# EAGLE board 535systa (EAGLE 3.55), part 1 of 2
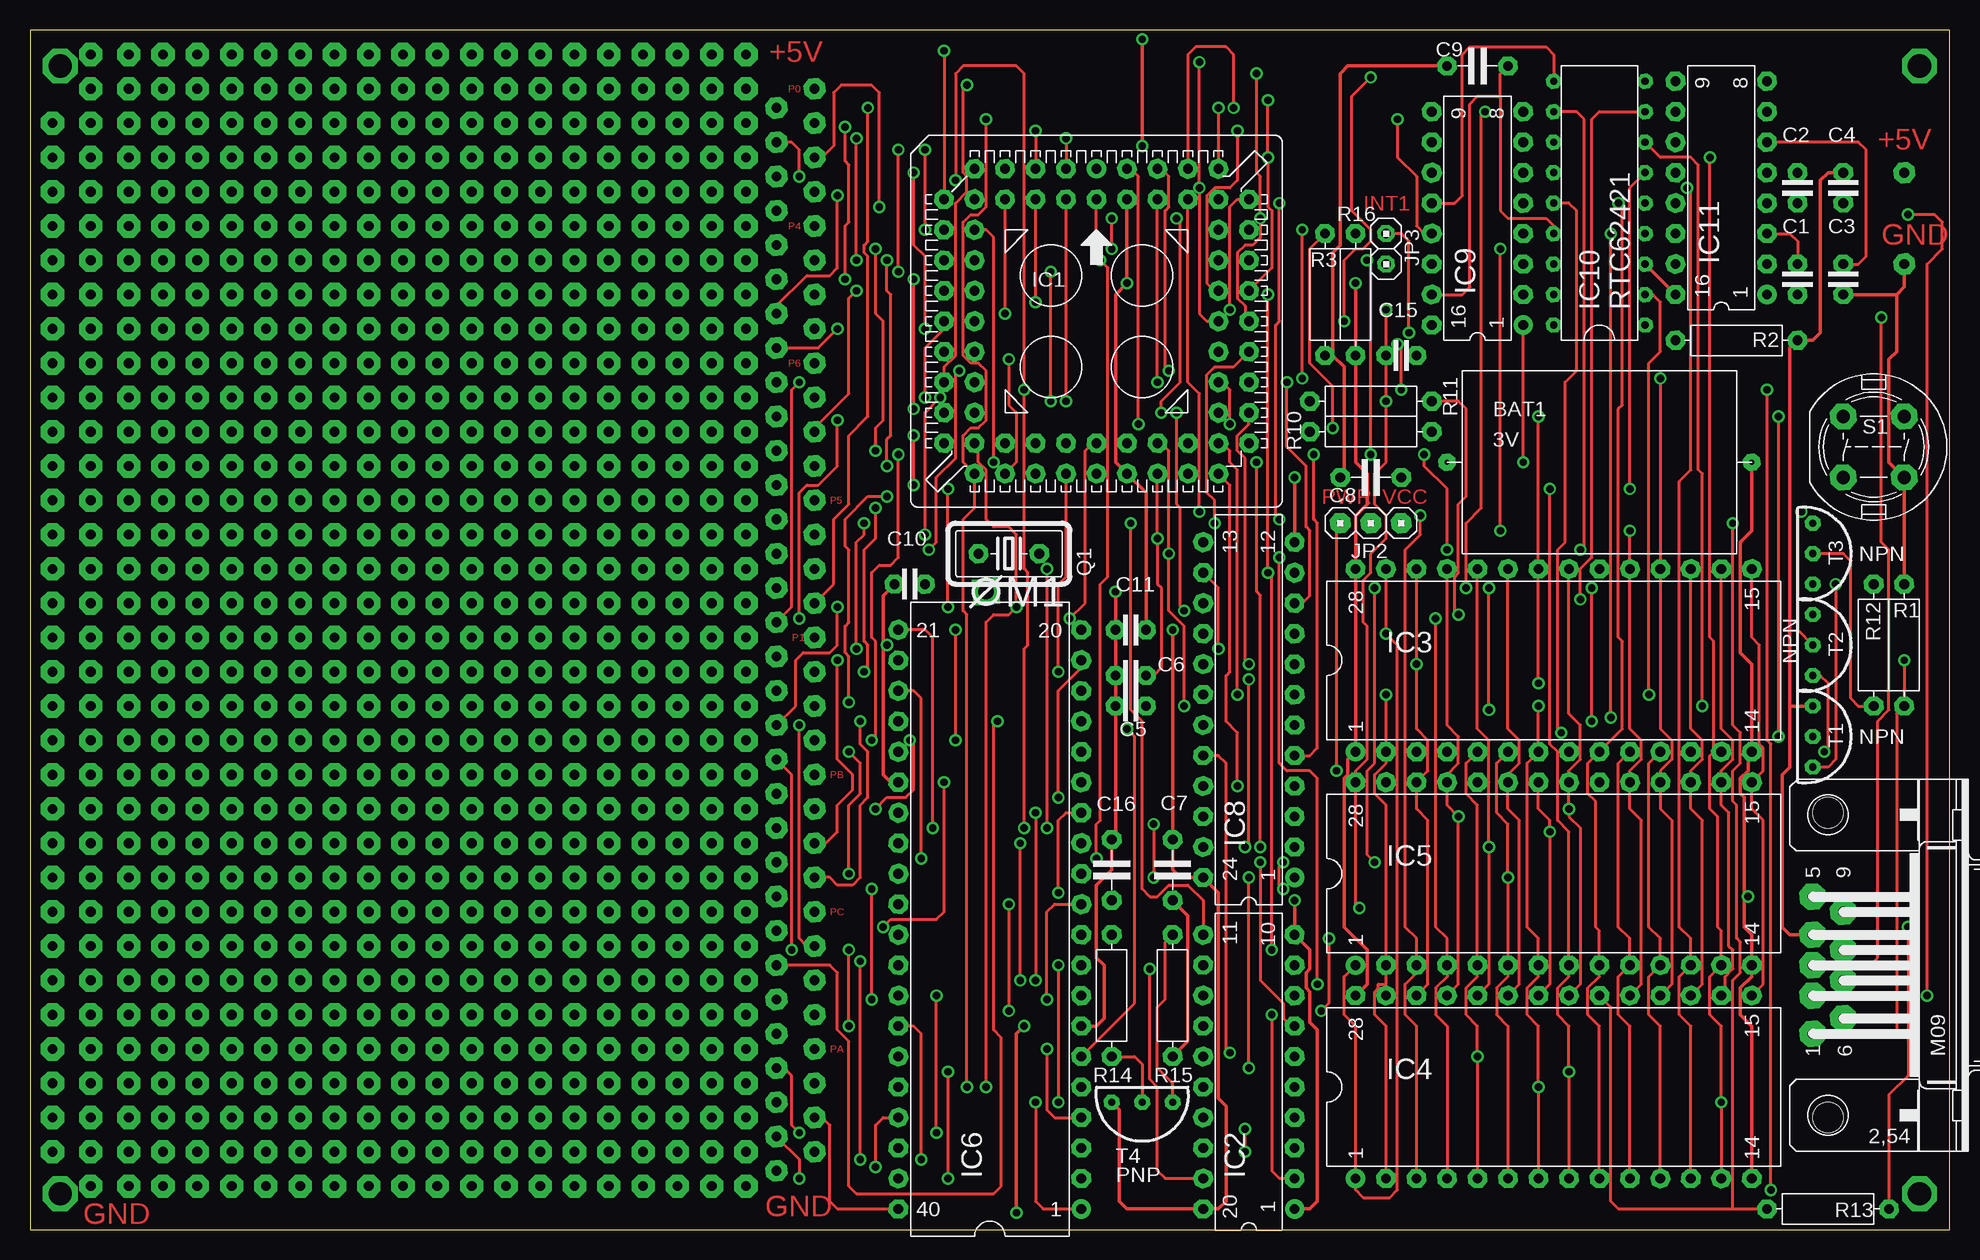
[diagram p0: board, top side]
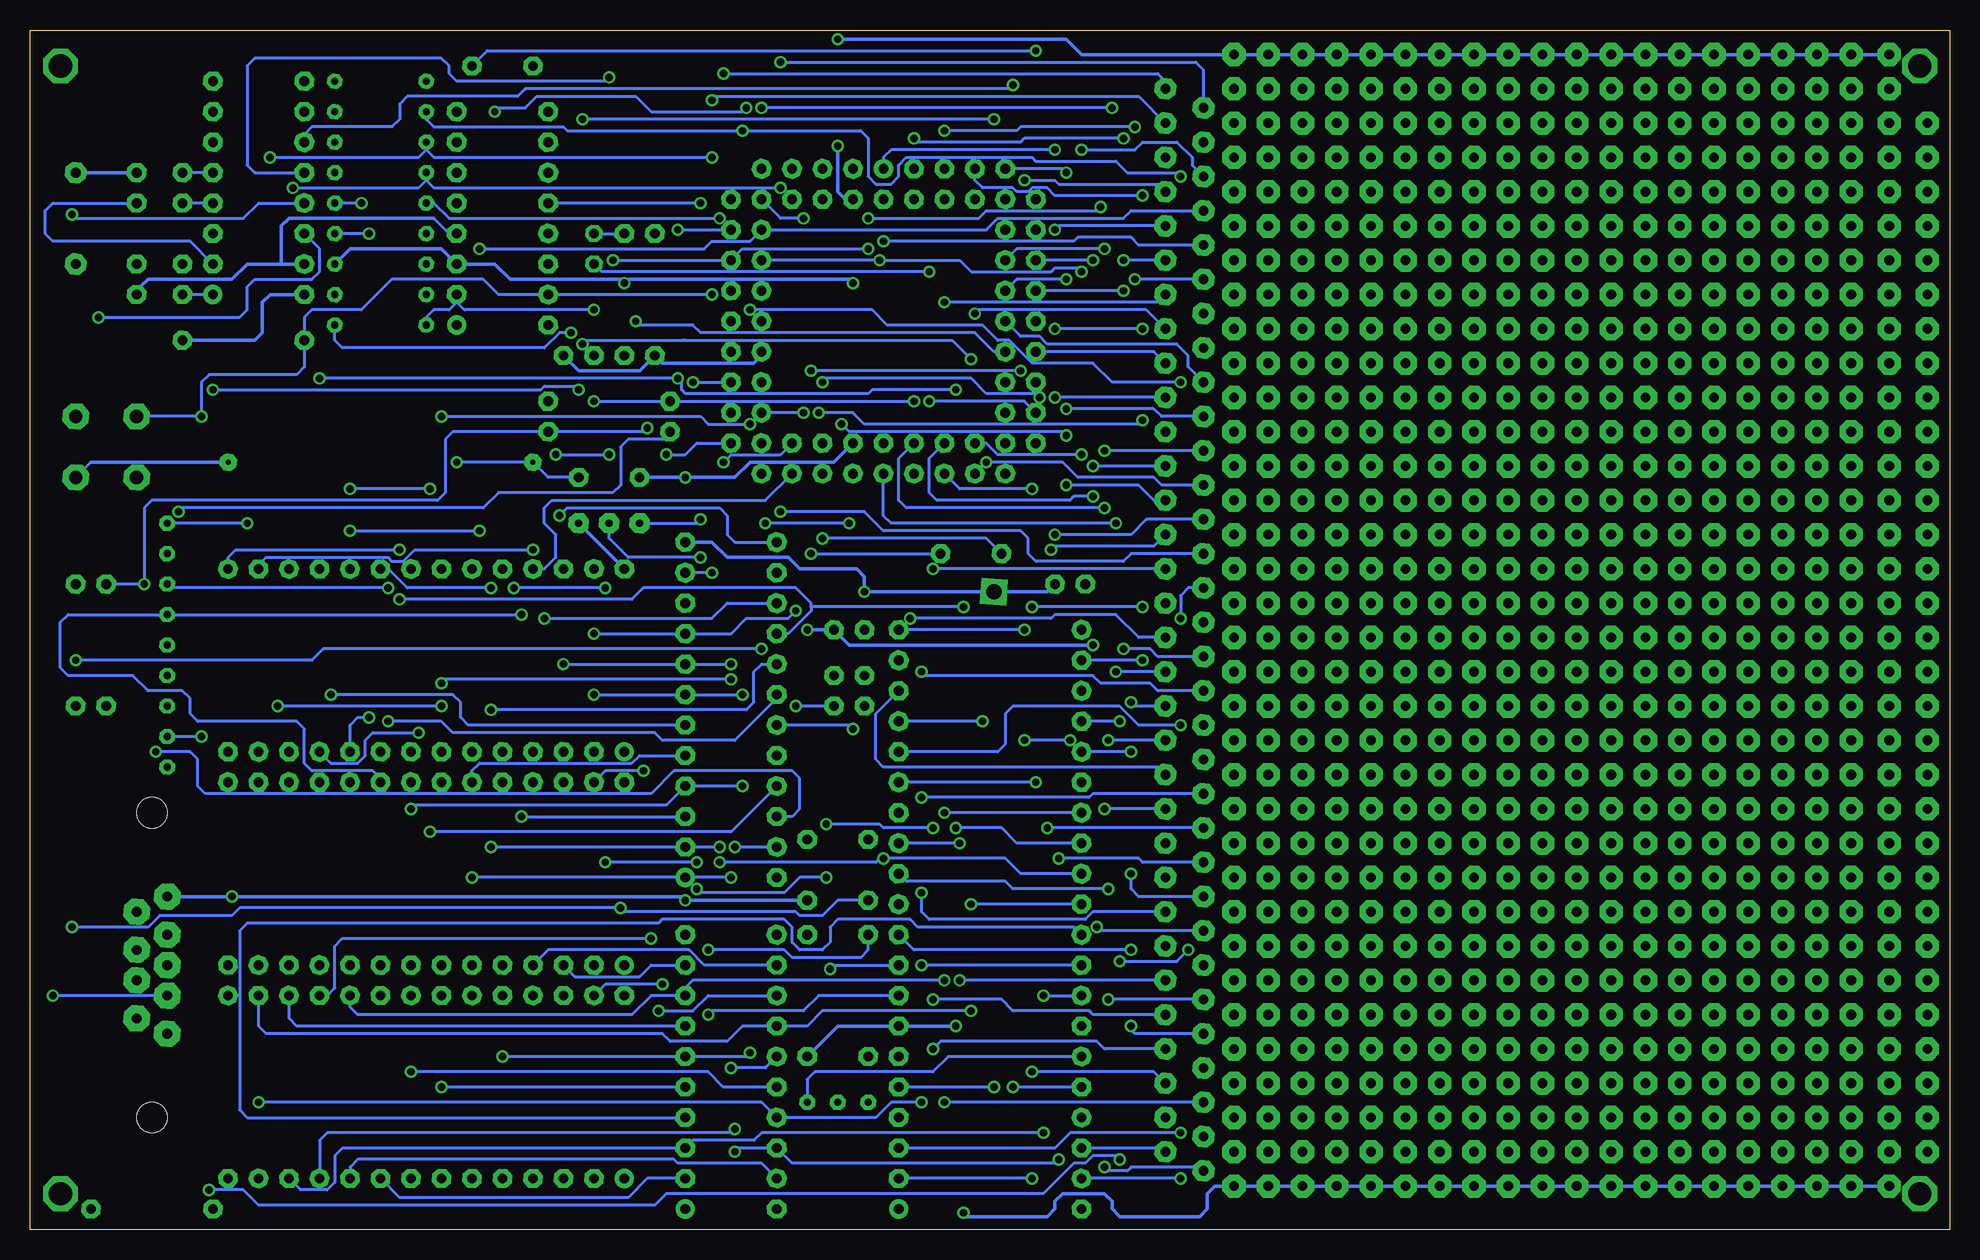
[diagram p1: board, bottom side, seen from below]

Size 159.99 x 99.97 mm. Coordinates in mm from the lower left corner, seen from the top.
Outline: 0,0 159.99,0 159.99,99.97 0,99.97 0,0
Copper layers used: Top, Bottom

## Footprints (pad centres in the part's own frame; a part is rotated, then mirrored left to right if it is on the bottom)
 = drill 0.406 pad 1.422 octagon:  -12.7,0;  12.7,0
2,5 = drill 0.813 pad 1.6 octagon:  -1.27,0;  1.27,0
5 = drill 0.813 pad 1.6 octagon:  -2.54,0;  2.54,0
8 = drill 0.813 pad 1.6 round:  0,12.7 | drill 0.813 pad 1.6 octagon:  0,10.16;  -2.54,12.7;  -2.54,10.16;  -5.08,12.7;  -5.08,10.16;  -7.62,12.7;  -7.62,10.16;  -10.16,12.7;  -12.7,10.16;  -10.16,10.16;  -12.7,7.62;  -10.16,7.62;  -12.7,5.08;  -10.16,5.08;  -12.7,2.54;  -10.16,2.54;  -12.7,0;  -10.16,0;  -12.7,-2.54;  -10.16,-2.54;  -12.7,-5.08;  -10.16,-5.08;  -12.7,-7.62;  -10.16,-7.62;  -12.7,-10.16;  -10.16,-12.7;  -10.16,-10.16;  -7.62,-12.7;  -7.62,-10.16;  -5.08,-12.7;  -5.08,-10.16;  -2.54,-12.7;  -2.54,-10.16;  0,-12.7;  0,-10.16;  2.54,-12.7;  2.54,-10.16;  5.08,-12.7;  5.08,-10.16;  7.62,-12.7;  7.62,-10.16;  10.16,-12.7;  12.7,-10.16;  10.16,-10.16;  12.7,-7.62;  10.16,-7.62;  12.7,-5.08;  10.16,-5.08;  12.7,-2.54;  10.16,-2.54;  12.7,0;  10.16,0;  12.7,2.54;  10.16,2.54;  12.7,5.08;  10.16,5.08;  12.7,7.62;  10.16,7.62;  12.7,10.16;  10.16,12.7;  10.16,10.16;  7.62,12.7;  7.62,10.16;  5.08,12.7;  5.08,10.16;  2.54,12.7;  2.54,10.16
L20 = drill 0.813 pad 1.6 round:  -11.43,-3.81 | drill 0.813 pad 1.6 octagon:  -8.89,-3.81;  -6.35,-3.81;  -3.81,-3.81;  -1.27,-3.81;  1.27,-3.81;  3.81,-3.81;  6.35,-3.81;  8.89,-3.81;  11.43,-3.81;  11.43,3.81;  8.89,3.81;  6.35,3.81;  3.81,3.81;  1.27,3.81;  -1.27,3.81;  -3.81,3.81;  -6.35,3.81;  -8.89,3.81;  -11.43,3.81
L28-6 = drill 0.813 pad 1.6 round:  -16.51,-7.62 | drill 0.813 pad 1.6 octagon:  -13.97,-7.62;  -11.43,-7.62;  -8.89,-7.62;  -6.35,-7.62;  -3.81,-7.62;  -1.27,-7.62;  1.27,-7.62;  3.81,-7.62;  6.35,-7.62;  8.89,-7.62;  11.43,-7.62;  13.97,-7.62;  16.51,-7.62;  16.51,7.62;  13.97,7.62;  11.43,7.62;  8.89,7.62;  6.35,7.62;  3.81,7.62;  1.27,7.62;  -1.27,7.62;  -3.81,7.62;  -6.35,7.62;  -8.89,7.62;  -11.43,7.62;  -13.97,7.62;  -16.51,7.62
L40 = drill 0.813 pad 1.6 round:  -24.13,-7.62 | drill 0.813 pad 1.6 octagon:  -21.59,-7.62;  -19.05,-7.62;  -16.51,-7.62;  -13.97,-7.62;  -11.43,-7.62;  -8.89,-7.62;  -6.35,-7.62;  -3.81,-7.62;  -1.27,-7.62;  1.27,-7.62;  3.81,-7.62;  6.35,-7.62;  8.89,-7.62;  11.43,-7.62;  13.97,-7.62;  16.51,-7.62;  19.05,-7.62;  21.59,-7.62;  24.13,-7.62;  24.13,7.62;  21.59,7.62;  19.05,7.62;  16.51,7.62;  13.97,7.62;  11.43,7.62;  8.89,7.62;  6.35,7.62;  3.81,7.62;  1.27,7.62;  -1.27,7.62;  -3.81,7.62;  -6.35,7.62;  -8.89,7.62;  -11.43,7.62;  -13.97,7.62;  -16.51,7.62;  -19.05,7.62;  -21.59,7.62;  -24.13,7.62
L24-3 = drill 0.813 pad 1.6 round:  -13.97,-3.81 | drill 0.813 pad 1.6 octagon:  -11.43,-3.81;  -8.89,-3.81;  -6.35,-3.81;  -3.81,-3.81;  -1.27,-3.81;  1.27,-3.81;  3.81,-3.81;  6.35,-3.81;  8.89,-3.81;  11.43,-3.81;  13.97,-3.81;  13.97,3.81;  11.43,3.81;  8.89,3.81;  6.35,3.81;  3.81,3.81;  1.27,3.81;  -1.27,3.81;  -3.81,3.81;  -6.35,3.81;  -8.89,3.81;  -11.43,3.81;  -13.97,3.81
L16 = drill 0.813 pad 1.6 round:  -8.89,-3.81 | drill 0.813 pad 1.6 octagon:  -6.35,-3.81;  -3.81,-3.81;  -1.27,-3.81;  1.27,-3.81;  3.81,-3.81;  6.35,-3.81;  8.89,-3.81;  8.89,3.81;  6.35,3.81;  3.81,3.81;  1.27,3.81;  -1.27,3.81;  -3.81,3.81;  -6.35,3.81;  -8.89,3.81
C62421 = drill 0.61 pad 1.27 octagon: 0 10.16,3.81; 1 7.62,3.81; 2 5.08,3.81; 3 2.54,3.81; 4 0,3.81; 5 -2.54,3.81; 6 -5.08,3.81; 7 -7.62,3.81; 8 -10.16,3.81;  -10.16,-3.81;  -7.62,-3.81;  -5.08,-3.81;  -2.54,-3.81;  0,-3.81;  2.54,-3.81;  5.08,-3.81;  7.62,-3.81;  10.16,-3.81
03 = drill 0.61 pad 1.676 octagon:  -2.54,0;  0,0;  2.54,0
02 = drill 0.813 pad 1.422 octagon:  -1.27,0;  1.27,0
TSTIFT = drill 1.27 pad 2.184 square:  0,0
18U-V = drill 0.813 pad 1.6 octagon:  -2.54,0;  2.54,0
10 = drill 0.813 pad 1.6 octagon:  -5.08,0;  5.08,0
6 = drill 1.118 pad 2.159 octagon:  -2.54,2.54;  2.54,2.54;  2.54,-2.54;  -2.54,-2.54
N-PNP = drill 0.61 pad 1.27 octagon:  -2.54,0;  0,0;  2.54,0
N-1 = drill 0.813 pad 1.778 octagon:  0,0
NN09 = drill 0.813 pad 2.184 octagon:  -5.715,1.27;  5.715,1.27;  0,1.27;  -2.54,1.27;  2.54,1.27;  -4.445,-1.27;  -1.27,-1.27;  1.27,-1.27;  4.445,-1.27 | hole 2.54: -12.7,0; 12.7,0

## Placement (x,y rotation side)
BAT1  3V  []  130.78,63.96 0 top
C1  10æ  [2,5]  147.29,79.2 90 top
C2  10æ  [2,5]  147.29,86.82 90 top
C3  10æ  [2,5]  151.1,79.2 90 top
C4  10æ  [2,5]  151.1,86.82 90 top
C5  22p  [2,5]  91.73,43.64 0 top
C6  22p  [2,5]  91.73,46.18 0 top
C7  100nF  [5]  95.22,29.98 270 top
C8  100nF  [5]  111.73,62.69 0 top
C9  100nF  [5]  120.62,96.98 0 top
C10  10æ  [2,5]  73.32,53.8 0 top
C11  680p  [2,5]  91.73,49.99 0 top
C15  10æF  [2,5]  114.27,72.85 0 top
C16  100nF  [5]  90.14,29.98 90 top
IC1  80C535  [8]  88.87,75.7 0 top
IC2  74373  [L20]  101.57,13.16 90 top
IC3  27C256  [L28-6]  126.97,47.45 0 top
IC4  28C256  [L28-6]  126.97,11.89 0 top
IC5  62256  [L28-6]  126.97,29.67 0 top
IC6  82C55A  [L40]  79.98,25.86 90 top
IC8  5C060  [L24-3]  101.57,43.32 90 top
IC9  MAX693  [L16]  120.62,84.28 90 top
IC10  RTC62421  [C62421]  130.78,85.55 90 top
IC11  MAX232  [L16]  140.94,86.82 90 top
JP2  CON03X1  [03]  111.73,58.88 0 top
JP3  CON02X1  [02]  113,81.74 90 top
M1  LTSTIFT  [TSTIFT]  79.67,53.16 0 top
Q1  12MHz  [18U-V]  81.57,56.34 0 top
R1  10k  [10]  156.18,48.72 90 top
R2  1k  [10]  142.21,74.12 0 top
R3  4k7  [10]  107.92,77.93 90 top
R10  4k7  [10]  111.73,66.5 0 top
R11  10k  [10]  111.73,69.04 0 top
R12  4k7  [10]  153.64,48.72 90 top
R13  10k  [10]  149.83,1.73 180 top
R14  4k7  [10]  90.14,19.51 90 top
R15  1k  [10]  95.22,19.51 90 top
R16  4k7  [10]  110.46,77.93 90 top
S1  DT6  [6]  153.64,65.23 0 top
T1  NPN  [N-PNP]  148.56,41.1 90 top
T2  NPN  [N-PNP]  148.56,48.72 90 top
T3  NPN  [N-PNP]  148.56,56.34 90 top
T4  PNP  [N-PNP]  92.68,10.62 0 top
U$1  PIN-1  [N-1]  65.38,95.07 0 top
U$2  PIN-1  [N-1]  62.2,93.48 0 top
U$3  PIN-1  [N-1]  65.38,92.21 0 top
U$4  PIN-1  [N-1]  62.2,90.63 0 top
U$5  PIN-1  [N-1]  65.38,89.36 0 top
U$6  PIN-1  [N-1]  62.2,87.77 0 top
U$7  PIN-1  [N-1]  65.38,86.5 0 top
U$8  PIN-1  [N-1]  62.2,84.91 0 top
U$9  PIN-1  [N-1]  65.38,49.35 0 top
U$10  PIN-1  [N-1]  62.2,47.76 0 top
U$11  PIN-1  [N-1]  65.38,46.49 0 top
U$12  PIN-1  [N-1]  62.2,44.91 0 top
U$13  PIN-1  [N-1]  65.38,43.64 0 top
U$14  PIN-1  [N-1]  62.2,42.05 0 top
U$15  PIN-1  [N-1]  65.38,40.78 0 top
U$16  PIN-1  [N-1]  62.2,39.19 0 top
U$17  PIN-1  [N-1]  65.38,83.64 0 top
U$18  PIN-1  [N-1]  62.2,82.05 0 top
U$19  PIN-1  [N-1]  65.38,80.78 0 top
U$20  PIN-1  [N-1]  62.2,79.2 0 top
U$21  PIN-1  [N-1]  65.38,77.93 0 top
U$22  PIN-1  [N-1]  62.2,76.34 0 top
U$23  PIN-1  [N-1]  65.38,75.07 0 top
U$24  PIN-1  [N-1]  62.2,73.48 0 top
U$25  PIN-1  [N-1]  65.38,60.78 0 top
U$26  PIN-1  [N-1]  62.2,59.19 0 top
U$27  PIN-1  [N-1]  65.38,57.92 0 top
U$28  PIN-1  [N-1]  62.2,56.34 0 top
U$29  PIN-1  [N-1]  65.38,55.07 0 top
U$30  PIN-1  [N-1]  62.2,53.48 0 top
U$31  PIN-1  [N-1]  65.38,52.21 0 top
U$32  PIN-1  [N-1]  62.2,50.62 0 top
U$33  PIN-1  [N-1]  65.38,72.21 0 top
U$34  PIN-1  [N-1]  62.2,70.62 0 top
U$35  PIN-1  [N-1]  65.38,69.35 0 top
U$36  PIN-1  [N-1]  62.2,67.77 0 top
U$37  PIN-1  [N-1]  65.38,66.5 0 top
U$38  PIN-1  [N-1]  62.2,64.91 0 top
U$39  PIN-1  [N-1]  65.38,63.64 0 top
U$40  PIN-1  [N-1]  62.2,62.05 0 top
U$41  PIN-1  [N-1]  65.38,15.06 0 top
U$42  PIN-1  [N-1]  62.2,13.47 0 top
U$43  PIN-1  [N-1]  65.38,12.2 0 top
U$44  PIN-1  [N-1]  62.2,10.62 0 top
U$45  PIN-1  [N-1]  65.38,9.35 0 top
U$46  PIN-1  [N-1]  62.2,7.76 0 top
U$47  PIN-1  [N-1]  65.38,6.49 0 top
U$48  PIN-1  [N-1]  62.2,4.9 0 top
U$49  PIN-1  [N-1]  65.38,37.92 0 top
U$50  PIN-1  [N-1]  62.2,36.33 0 top
U$51  PIN-1  [N-1]  65.38,35.06 0 top
U$52  PIN-1  [N-1]  62.2,33.48 0 top
U$53  PIN-1  [N-1]  65.38,32.21 0 top
U$54  PIN-1  [N-1]  62.2,30.62 0 top
U$55  PIN-1  [N-1]  65.38,29.35 0 top
U$56  PIN-1  [N-1]  62.2,27.76 0 top
U$57  PIN-1  [N-1]  65.38,26.49 0 top
U$58  PIN-1  [N-1]  62.2,24.9 0 top
U$59  PIN-1  [N-1]  65.38,23.63 0 top
U$60  PIN-1  [N-1]  62.2,22.05 0 top
U$61  PIN-1  [N-1]  65.38,20.78 0 top
U$62  PIN-1  [N-1]  62.2,19.19 0 top
U$63  PIN-1  [N-1]  65.38,17.92 0 top
U$64  PIN-1  [N-1]  62.2,16.33 0 top
U$65  PIN-1  [N-1]  156.18,88.09 0 top
U$66  PIN-1  [N-1]  156.18,80.47 0 top
X1  9 pol  [NN09]  149.83,22.05 90 top

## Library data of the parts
BAT1 = BATTERY
C1-C11 C15 C16 R1-R3 R10-R16 = DISCRETE
IC1 = INTEL
IC2 = 74XX
IC3 IC4 = MEMNEC
IC5 = MEMHITCH
IC6 = HARRIS
IC8 = PAL
IC9 IC11 = MAXIM
IC10 = Clock
JP2 JP3 M1 = CONNECT
Q1 = QUARTZ
S1 = KEY
T1-T4 = LINEAR
U$1-U$66 = CONQUICK
X1 = SUBD-A

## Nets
A0: IC2. IC3. IC4. IC5. IC6. IC10.
A1: IC2. IC3. IC4. IC5. IC6. IC10.
A2: IC2. IC3. IC4. IC5. IC10.
A3: IC2. IC3. IC4. IC5. IC10.
A4: IC2. IC3. IC4. IC5. IC8.
A5: IC2. IC3. IC4. IC5. IC8.
A6: IC2. IC3. IC4. IC5. IC8.
A7: IC2. IC3. IC4. IC5. IC8.
A8: IC1. IC3. IC4. IC5. IC8.
A9: IC1. IC3. IC4. IC5. IC8.
A10: IC1. IC3. IC4. IC5. IC8.
A11: IC1. IC3. IC4. IC5. IC8.
A12: IC1. IC3. IC4. IC5. IC8.
A13: IC1. IC3. IC4. IC5. IC8.
A14: IC1. IC3. IC4. IC5. IC8.
A15: IC1. IC8.
ALE: IC1. IC2.
CS_E^2: IC8. T3.
CS_PIO: IC6. IC8.
CS_PROM: IC3. IC8.
CS_RAM: IC8. T2.
CS_RTC: IC8. IC10.
GND: BAT1. C3. C5. C6. C7. C8. C9. C10. C11. C15. C16. IC1. IC2. IC3. IC4. IC5. IC6. IC8. IC9. IC11. M1. R1. R3. R15. S1. U$66. X1.
INT0: IC1.
INT1: IC1. JP3.
MODE: IC8. R1. X1.
N$1: BAT1. C8. IC9.
N$2: R3. R10. R12. T1.
N$3: R12. T3.
N$4: R10. T2.
N$5: IC4. R13. T3.
N$6: IC5. R11. T2.
N$7: C4. IC11.
N$8: C3. IC11.
N$9: IC6. R15. T4.
N$11: C1. IC11.
N$12: C1. IC11.
N$13: C2. IC11.
N$14: C2. IC11.
N$15: IC11. X1.
N$16: IC11. X1.
N$18: R14. T4.
N$19: IC10. JP3. R16.
N$21: IC4. JP2.
N$34: C5. IC1. Q1.
N$35: C6. IC1. Q1.
P00: IC1. IC2. IC3. IC4. IC5. IC6. IC10.4 U$1.
P01: IC1. IC2. IC3. IC4. IC5. IC6. IC10.3 U$2.
P02: IC1. IC2. IC3. IC4. IC5. IC6. IC10.2 U$3.
P03: IC1. IC2. IC3. IC4. IC5. IC6. IC10.1 U$4.
P04: IC1. IC2. IC3. IC4. IC5. IC6. U$5.
P05: IC1. IC2. IC3. IC4. IC5. IC6. U$6.
P06: IC1. IC2. IC3. IC4. IC5. IC6. U$7.
P07: IC1. IC2. IC3. IC4. IC5. IC6. U$8.
P10: IC1. U$9.
P11: IC1. U$10.
P12: IC1. U$11.
P13: IC1. U$12.
P14: IC1. U$13.
P15: IC1. U$14.
P16: IC1. U$15.
P17: IC1. U$16.
P40: IC1. U$17.
P41: IC1. U$18.
P42: IC1. U$19.
P43: IC1. U$20.
P44: IC1. U$21.
P45: IC1. U$22.
P46: IC1. U$23.
P47: IC1. U$24.
P50: IC1. U$25.
P51: IC1. U$26.
P52: IC1. U$27.
P53: IC1. U$28.
P54: IC1. U$29.
P55: IC1. U$30.
P56: IC1. U$31.
P57: IC1. U$32.
P60: IC1. U$33.
P61: IC1. U$34.
P62: IC1. U$35.
P63: IC1. U$36.
P64: IC1. U$37.
P65: IC1. U$38.
P66: IC1. U$39.
P67: IC1. U$40.
PA0: IC6. U$41.
PA1: IC6. U$42.
PA2: IC6. U$43.
PA3: IC6. U$44.
PA4: IC6. U$45.
PA5: IC6. U$46.
PA6: IC6. U$47.
PA7: IC6. U$48.
PB0: IC6. U$49.
PB1: IC6. U$50.
PB2: IC6. U$51.
PB3: IC6. U$52.
PB4: IC6. U$53.
PB5: IC6. U$54.
PB6: IC6. U$55.
PB7: IC6. U$56.
PC0: IC6. U$57.
PC1: IC6. U$58.
PC2: IC6. U$59.
PC3: IC6. U$60.
PC4: IC6. U$61.
PC5: IC6. U$62.
PC6: IC6. U$63.
PC7: IC6. U$64.
PSEN: IC1. IC3. IC8.
PWR: IC5. IC9. IC10.0 JP2.
RD: IC1. IC6. IC8. IC10.
RESET: C9. IC1. IC8. IC9. IC10.5 R2. R14. S1. T1.
RXD: IC1. IC11.
TXD: IC1. IC11.
VAGND: IC1.
VAREF: IC1.
VCC: C4. C7. C10. C11. IC1. IC2. IC3. IC4. IC6. IC8. IC9. IC10. IC11. JP2. R2. R16. T1. T4. U$65. X1.
VN: IC4. IC5. IC8.
VPD: C15. C16. IC1. IC5. IC9. IC10.8 R11. R13.
WR: IC1. IC6. IC9.

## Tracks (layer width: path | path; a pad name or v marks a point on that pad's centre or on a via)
A0  (via drill 0.61 pad 1.02)
  Top 0.254: 133.32,4.27 133.32,16.97 132.37,17.92 132.37,21.09 133.32,22.05 133.32,24.27 132.37,25.22 132.37,38.87 133.32,39.83 | v93.32,21.73 93.32,12.52 93.95,11.89 93.95,4.9 94.59,4.27 97.76,4.27 | v131.74,42.68 v131.74,83.01
  Bottom 0.254: 97.76,4.27 99.03,5.54 106.02,5.54 106.34,5.85 132.69,5.85 133.32,5.22 133.32,4.27 | v93.32,21.73 93,22.05 87.6,22.05 | v131.74,42.68 132.69,42.68 133.32,42.05 133.32,39.83 | v131.74,83.01 134.59,83.01
A1  (via drill 0.61 pad 1.02)
  Top 0.254: 130.78,4.27 130.78,16.97 129.83,17.92 129.83,20.14 130.78,21.09 130.78,22.05 130.78,24.91 130.47,25.22 130.47,35.7 129.83,36.33 129.83,38.87 130.78,39.83 132.69,41.73 132.69,49.04 132.37,49.35 132.37,68.4 132.69,68.72 132.69,85.23 v132.37,85.55 | v103.48,17.92 103.48,4.9 104.11,4.27 105.38,4.27
  Bottom 0.254: 105.38,4.27 108.56,4.27 110.15,2.68 129.2,2.68 130.78,4.27 | 87.6,19.51 94.27,19.51 95.54,18.24 103.16,18.24 v103.48,17.92 | v132.37,85.55 134.59,85.55
A2  (via drill 0.61 pad 1.02)
  Top 0.254: 128.24,4.27 v128.24,13.16 128.24,16.97 127.29,17.92 127.29,20.14 128.24,21.09 128.24,22.05 128.24,33.16 127.29,34.11 127.29,39.83 | 127.29,39.83 128.24,39.83 | v133.32,61.74 133.32,86.82 134.59,88.09 | v126.66,61.74 126.66,40.46 127.29,39.83
  Bottom 0.254: v128.24,13.16 103.48,13.16 102.21,11.89 97.76,11.89 | v126.66,61.74 v133.32,61.74
A3  (via drill 0.61 pad 1.02)
  Top 0.254: 125.7,4.27 v125.7,11.89 125.7,16.97 124.75,17.92 124.75,20.14 125.7,21.09 125.7,22.05 125.7,24.27 124.75,25.22 124.75,38.87 125.7,39.83 v125.7,43.64 | v139.36,43.64 139.36,63 139.04,63.32 139.04,88.72 138.4,89.36 135.86,89.36 134.59,90.63
  Bottom 0.254: 105.38,11.89 v125.7,11.89 | v125.7,43.64 v139.36,43.64
A4  (via drill 0.61 pad 1.02)
  Top 0.254: v101.57,13.48 v101.57,29.35 | 123.16,4.27 123.16,16.97 122.21,17.92 122.21,20.14 123.16,21.09 123.16,22.05 v123.16,29.35 123.16,33.79 122.21,34.75 122.21,38.87 123.16,39.83
  Bottom 0.254: v101.57,13.48 98.72,13.48 97.76,14.43 | v101.57,29.35 105.38,29.35 v123.16,29.35
A5  (via drill 0.61 pad 1.02)
  Top 0.254: 120.62,4.27 v120.62,14.43 120.62,16.97 119.67,17.92 119.67,20.14 120.62,21.09 120.62,22.05 120.62,35.38 119.67,36.33 119.67,38.87 120.62,39.83 | v99.99,14.74 99.67,15.06 99.67,38.87 99.03,39.51 97.76,39.51
  Bottom 0.254: v120.62,14.43 105.38,14.43 100.3,14.43 v99.99,14.74
A6  (via drill 0.61 pad 1.02)
  Top 0.254: 118.08,4.27 118.08,16.97 117.13,17.92 117.13,20.14 118.08,21.09 118.08,22.05 118.08,24.27 117.13,25.22 117.13,39.83 | 117.13,39.83 118.08,39.83 | 117.13,39.83 v117.13,50.94
  Bottom 0.254: 118.08,22.05 116.81,23.32 105.07,23.32 103.8,22.05 97.76,22.05 | v117.13,50.94 103.16,50.94 101.89,52.21 97.76,52.21
A7  (via drill 0.61 pad 1.02)
  Top 0.254: 115.54,4.27 115.54,16.97 114.59,17.92 114.59,20.46 115.54,21.41 115.54,22.05 115.54,24.27 114.59,25.22 114.59,39.83 | 114.59,39.83 115.54,39.83 | v115.86,59.51 115.86,57.93 114.59,56.65 114.59,39.83
  Bottom 0.254: 115.54,22.05 114.59,21.09 109.19,21.09 108.24,22.05 105.38,22.05 | v115.86,59.51 115.23,60.15 102.53,60.15 101.89,59.51 101.89,57.93 101.26,57.29 97.76,57.29
A8  (via drill 0.61 pad 1.02)
  Top 0.254: 118.08,19.51 119.04,20.46 v119.04,34.43 118.08,35.38 118.08,37.29 118.08,37.92 119.04,38.87 119.04,41.1 118.08,42.05 118.08,55.07
  Bottom 0.254: 96.49,63 98.72,60.78 116.5,60.78 117.13,60.15 117.13,58.88 116.18,57.93 116.18,56.02 117.13,55.07 118.08,55.07 | v119.04,34.43 105.38,34.43
A9  (via drill 0.61 pad 1.02)
  Top 0.254: 121.58,37.29 v121.58,31.89 121.58,20.46 120.62,19.51 | 121.58,37.29 120.62,37.29 | 121.58,37.29 121.58,40.78 120.62,41.73 120.62,55.07 | v102.21,63.96 102.21,53.16 102.53,52.85 v102.53,31.89
  Bottom 0.254: v102.21,63.96 101.57,64.59 97.45,64.59 96.49,65.55 | v102.53,31.89 105.38,31.89 v121.58,31.89
A10  (via drill 0.61 pad 1.02)
  Top 0.254: v100.62,36.97 100.62,41.42 99.67,42.37 99.67,46.18 99.99,46.5 99.99,62.05 99.03,63 | 128.24,19.51 129.2,20.46 129.2,33.48 128.24,34.43 v128.24,35.07 128.24,37.29 128.24,38.24 129.2,39.19 129.2,42.05 128.24,43 128.24,55.07
  Bottom 0.254: v100.62,36.97 105.38,36.97 106.97,35.38 127.93,35.38 v128.24,35.07
A11  (via drill 0.61 pad 1.02)
  Top 0.254: v106.97,64.59 106.97,59.19 107.29,58.88 107.29,40.15 106.65,39.51 105.38,39.51 | 123.16,19.51 124.12,20.46 124.12,34.11 123.16,35.07 123.16,37.29 123.16,37.92 124.12,38.87 124.12,40.78 123.16,41.73 123.16,55.07
  Bottom 0.254: v106.97,64.59 105.38,64.59 104.43,65.55 101.57,65.55 | 105.38,39.51 109.19,39.51 109.83,38.87 122.53,38.87 123.16,38.24 123.16,37.29
A12  (via drill 0.61 pad 1.02)
  Top 0.254: v100.62,44.59 100.62,63.32 99.99,63.96 99.99,64.91 99.35,65.55 99.03,65.55 | 113,4.27 113,16.97 112.05,17.92 112.05,19.82 112.37,20.14 112.37,20.46 113,20.46 113,22.05 113,35.38 112.05,36.33 112.05,37.92 113,38.87 113,39.83 v113,44.59
  Bottom 0.254: v100.62,44.59 105.38,44.59 v113,44.59
A13  (via drill 0.61 pad 1.02)
  Top 0.254: v101.57,47.13 101.26,47.45 101.26,64.28 100.62,64.91 100.62,66.18 101.57,67.13 101.57,68.08 | 115.54,19.51 116.5,20.46 116.5,34.11 115.54,35.07 115.54,37.29 116.5,38.24 116.5,40.78 115.54,41.73 v115.54,47.13 115.54,55.07
  Bottom 0.254: v101.57,47.13 105.38,47.13 v115.54,47.13
A14  (via drill 0.61 pad 1.02)
  Top 0.254: 110.46,22.05 109.51,21.09 109.51,17.92 110.46,16.97 110.46,4.27 110.46,3.31 111.1,2.68 113.32,2.68 113.96,3.31 113.96,48.72 v113,49.67 113,55.07 | v95.54,68.08 95.54,60.47 95.86,60.15 95.86,51.89 v96.18,51.57
  Bottom 0.254: v113,49.67 105.38,49.67 101.57,49.67 100.3,50.94 96.81,50.94 v96.18,51.57 | v95.54,68.08 99.03,68.08
A15  (via drill 0.61 pad 1.02)
  Top 0.254: v104.75,70.63 104.75,65.23 106.34,63.64 106.34,58.56 106.65,58.24 106.65,52.85 106.02,52.21 105.38,52.21
  Bottom 0.254: v104.75,70.63 101.57,70.63
ALE  (via drill 0.61 pad 1.02)
  Top 0.254: v98.72,58.88 98.72,60.78 98.08,61.42 98.08,71.26 98.72,71.9 100.3,71.9 101.57,73.16 | v91.73,58.88 91.73,43.32 92.68,42.37 92.68,28.4 93.32,27.76 93.95,27.76 94.91,28.72 96.49,28.72 97.76,27.45 97.76,24.59
  Bottom 0.254: v91.73,58.88 v98.72,58.88
CS_E^2  (via drill 0.61 pad 1.02)
  Top 0.254: v130.15,42.37 v130.15,53.48
  Bottom 0.254: v130.15,42.37 125.7,42.37 124.75,41.42 107.92,41.42 107.29,40.78 101.26,40.78 97.76,44.27 97.76,44.59 | v130.15,53.48 148.25,53.48 148.56,53.8
CS_PIO  (via drill 0.61 pad 1.02)
  Top 0.254: 87.6,14.43 92.05,18.87 92.05,41.1 v91.41,41.73
  Bottom 0.254: v91.41,41.73 91.73,42.05 97.76,42.05
CS_PROM  (via drill 0.61 pad 1.02)
  Top 0.254: v121.58,43.32 v121.58,53.48
  Bottom 0.254: 130.78,55.07 130.15,55.07 128.56,53.48 v121.58,53.48 | v121.58,43.32 100.3,43.32 99.67,43.96 99.67,46.5 99.03,47.13 97.76,47.13
CS_RAM  (via drill 0.61 pad 1.02)
  Top 0.254: v149.52,39.83 149.83,40.15 149.83,45.54 149.2,46.18 148.56,46.18
  Bottom 0.254: 97.76,34.43 96.49,34.43 95.86,35.07 95.86,37.61 96.49,38.24 106.34,38.24 108.24,36.33 145.39,36.33 146.02,36.97 146.02,39.19 146.66,39.83 v149.52,39.83
CS_RTC  (via drill 0.61 pad 1.02)
  Top 0.254: v134.91,44.59 134.91,72.21 135.86,73.16 135.86,77.29 135.23,77.93 134.59,77.93
  Bottom 0.254: v134.91,44.59 124.75,44.59 124.12,43.96 124.12,42.68 123.48,42.05 105.38,42.05
GND  (via drill 0.61 pad 1.02, 0.81 pad 1.93)
  Top 0.254: v143.17,27.76 142.85,27.76
  Top 0.305: R1. 156.18,62.69 154.91,63.96 154.91,72.53 155.55,73.16 155.55,77.93 | 143.48,4.27 143.48,16.97 142.53,17.92 142.53,20.14 143.48,21.09 143.48,22.05 143.48,24.59 142.85,25.22 142.85,27.76 142.85,36.02 142.53,36.33 142.53,37.61 143.17,38.24 143.17,39.51 143.48,39.83 143.48,47.13 142.53,48.08 142.53,57.29 143.48,58.24 BAT1. | 155.55,77.93 151.1,77.93 | 105.38,57.29 v105.38,62.69 | 108.56,72.85 108.56,81.42 109.19,82.05 109.19,96.34 109.83,96.98 118.08,96.98 | 109.19,62.69 109.51,63 109.51,71.9 108.56,72.85 | 108.56,72.85 107.92,72.85 | 105.38,1.73 106.65,1.73 107.29,2.36 107.29,16.65 106.65,17.29 106.65,19.82 106.34,20.14 106.34,21.41 106.65,21.73 106.65,23.32 105.38,24.59 v105.38,27.45 | C7. 96.49,26.18 96.49,15.7 95.22,14.43 | v90.46,53.16 90.46,49.99 90.46,46.18 90.46,43.64 90.46,32.84 C16. 90.14,29.98 88.87,28.72 88.87,22.68 89.51,22.05 89.51,17.6 88.87,16.97 87.6,16.97 | v82.21,1.41 82.21,16.33 v82.84,16.97 | U$66. 156.18,78.56 155.55,77.93
  Bottom 0.254: 150.79,78.56 151.1,78.56 151.1,77.93 | 126.34,84.28 125.07,83.01 124.43,83.01 | 154.91,63.96 156.18,62.69 | v105.38,27.45 105.7,27.76
  Bottom 0.305: 150.79,78.56 150.15,79.2 143.17,79.2 141.9,80.47 137.13,80.47 139.04,80.47 139.04,83.64 138.4,84.28 126.34,84.28 | BAT1. 154.91,63.96 | 148.56,27.76 v143.17,27.76 105.7,27.76 | 91.41,65.55 93,63.96 99.99,63.96 101.26,62.69 v105.38,62.69 109.19,62.69 | 99.03,73.16 99.03,72.85 99.67,72.21 107.29,72.21 107.92,72.85 109.19,71.58 114.27,71.58 C15. | 95.22,14.43 92.68,16.97 87.6,16.97 v82.84,16.97 | C10. 75.22,53.16 M1. v90.46,53.16 90.46,54.43 91.1,55.07 95.86,55.07 96.81,56.02 101.89,56.02 103.16,57.29 105.38,57.29 | C7. v105.38,27.45 | v5.05,3.63 v8.23,3.63 v11.09,3.63 v13.94,3.63 v16.8,3.63 v19.66,3.63 v22.52,3.63 v25.37,3.63 v28.23,3.63 v31.09,3.63 v33.95,3.63 v36.8,3.63 v39.66,3.63 v42.52,3.63 v45.38,3.63 v48.23,3.63 v51.09,3.63 v53.95,3.63 v56.81,3.63 v59.66,3.63 61.25,3.63 61.89,3 61.89,1.73 62.52,1.09 69.19,1.09 69.82,1.73 69.82,2.36 70.46,3 73.95,3 74.59,2.36 74.59,1.73 75.22,1.09 81.89,1.09 v82.21,1.41
INT1  (via drill 0.61 pad 1.02)
  Top 0.254: v85.06,69.04 v85.06,79.83
  Bottom 0.254: v85.06,69.04 77.13,69.04 76.17,68.08 | v85.06,79.83 112.37,79.83 113,80.47
MODE  (via drill 0.61 pad 1.02)
  Top 0.254: v99.03,48.4 99.03,53.48 97.76,54.75 | v156.18,47.45 156.18,43.64 155.55,43 155.55,16.65 154.91,16.01 148.88,16.01 148.56,16.33
  Bottom 0.254: v99.03,48.4 135.55,48.4 136.5,47.45 v156.18,47.45
N$1  (via drill 0.61 pad 1.02)
  Top 0.254: v124.43,63.96 124.43,75.39
  Bottom 0.254: C8. 116.81,62.69 118.08,63.96 v124.43,63.96
N$2  (via drill 0.61 pad 1.02)
  Top 0.254: v150.47,53.8 150.47,39.19 149.83,38.56 148.56,38.56 | v108.56,66.82 108.56,70.31 106.65,72.21 106.65,81.74 R3.
  Bottom 0.254: R12. v150.47,53.8 150.47,60.15 149.83,60.78 126.02,60.78 125.39,61.42 125.39,65.86 124.75,66.5 R10. 108.88,66.5 v108.56,66.82
N$3
  Top 0.254: 153.64,43.64 152.37,43.64 151.74,44.27 151.74,55.7 151.1,56.34 148.56,56.34
N$4  (via drill 0.61 pad 1.02)
  Top 0.254: v147.61,59.83 147.29,59.51 147.29,49.99 148.56,48.72
  Bottom 0.254: v147.61,59.83 147.29,60.15 122.21,60.15 120.94,61.42 111.42,61.42 110.78,62.05 110.78,65.23 110.15,65.86 107.29,65.86 106.65,66.5
N$5  (via drill 0.61 pad 1.02)
  Top 0.254: 141.9,1.73 132.37,1.73 131.74,2.36 131.74,18.56 130.78,19.51 | 141.9,1.73 R13. | v141.9,58.88 141.9,42.05 142.53,41.42 142.53,38.87 141.9,38.24 141.9,35.7 142.21,35.38 142.21,24.27 142.53,23.95 142.53,21.41 141.9,20.78 141.9,1.73
  Bottom 0.254: v141.9,58.88 T3.
N$6  (via drill 0.61 pad 1.02)
  Top 0.254: v119.04,51.26 118.72,51.57 118.72,54.43 119.04,54.75 119.04,60.47 119.67,61.1 119.67,68.4 119.04,69.04 R11.
  Bottom 0.254: 130.78,37.29 130.78,37.61 131.42,38.24 136.5,38.24 137.13,38.87 137.13,41.73 137.77,42.37 146.02,42.37 146.66,43 146.66,44.27 147.29,44.91 150.15,44.91 151.42,46.18 156.82,46.18 157.45,46.81 157.45,50.62 156.82,51.26 T2. v119.04,51.26
N$7
  Bottom 0.254: 144.75,80.47 146.66,82.37 158.09,82.37 158.72,83.01 158.72,84.91 158.09,85.55 151.1,85.55
N$8
  Top 0.254: C3. 152.37,80.47 153.01,81.1 153.01,89.99 152.37,90.63 144.75,90.63
N$9
  Top 0.254: R15. 94.59,23.95 94.59,19.19 93.95,18.56 93.95,13.48 95.22,12.21 T4.
  Bottom 0.254: 72.36,14.43 83.48,14.43 84.75,13.16 94.59,13.16 95.22,12.52 T4.
N$10  (via drill 0.81 pad 1.93)
  other vias: 59.66,95.07
N$11
  Bottom 0.254: 144.75,77.93 147.29,77.93
N$12
  Top 0.254: 144.75,83.01 146.66,83.01 147.29,82.37 C1.
N$13
  Bottom 0.254: 144.75,85.55 147.29,85.55
N$14
  Bottom 0.254: 144.75,88.09 C2.
N$15  (via drill 0.61 pad 1.02)
  Top 0.254: v156.5,84.6 158.72,84.6 159.36,83.96 159.36,81.74 158.09,80.47 v158.09,19.51
  Bottom 0.254: v156.5,84.6 156.18,84.28 142.21,84.28 140.94,85.55 137.13,85.55 | 148.56,19.51 v158.09,19.51
N$16  (via drill 0.61 pad 1.02)
  Top 0.254: v154.28,76.02 154.28,57.29 154.91,56.65 154.91,43.32 153.96,42.37 153.96,22.68 153.33,22.05 148.56,22.05
  Bottom 0.254: 137.13,83.01 135.86,81.74 135.86,79.83 136.5,79.2 141.26,79.2 141.9,78.56 141.9,76.66 142.53,76.02 v154.28,76.02
N$17  (via drill 0.81 pad 1.93)
  other vias: 59.66,92.21
N$18
  Top 0.254: 92.68,10.62 92.68,13.79 92.05,14.43 90.14,14.43
N$19  (via drill 0.61 pad 1.02)
  Top 0.254: v114.91,74.75 114.91,82.37 114.27,83.01 JP3.
  Bottom 0.254: v114.91,74.75 115.86,74.75 117.13,73.48 133.96,73.48 134.59,74.12 134.59,75.39 | JP3. R16.
N$20  (via drill 0.81 pad 1.93)
  other vias: 59.66,89.36
N$21  (via drill 0.61 pad 1.02)
  Top 0.254: v107.29,20.46 107.29,37.61 106.65,38.24 104.75,38.24 104.11,38.87 v104.11,56.02
  Bottom 0.254: v107.29,20.46 112.05,20.46 113,19.51 | v104.11,56.02 110.15,56.02 111.73,57.61 111.73,58.88
N$22  (via drill 1.93 pad 2.54)
  other vias: 157.45,3
N$23  (via drill 0.81 pad 1.93)
  other vias: 59.66,86.5
N$24  (via drill 0.81 pad 1.93)
  other vias: 59.66,83.64
N$25  (via drill 1.93 pad 2.54)
  other vias: 157.45,96.98
N$26  (via drill 1.93 pad 2.54)
  other vias: 2.51,3
N$27  (via drill 1.93 pad 2.54)
  other vias: 2.51,96.98
N$28  (via drill 0.81 pad 1.93)
  other vias: 59.66,80.78
N$29  (via drill 0.81 pad 1.93)
  other vias: 59.66,77.93
N$30  (via drill 0.81 pad 1.93)
  other vias: 59.66,75.07
N$31  (via drill 0.81 pad 1.93)
  other vias: 59.66,72.21
N$32  (via drill 0.81 pad 1.93)
  other vias: 59.66,69.35
N$33  (via drill 0.81 pad 1.93)
  other vias: 59.66,66.5
N$34  (via drill 0.61 pad 1.02)
  Top 0.254: 93.95,65.55 94.27,65.55 94.91,64.91 v94.91,56.34 94.91,51.57 96.18,50.3 v96.18,43.64
  Bottom 0.254: v94.91,56.34 Q1. | C5. v96.18,43.64
N$35  (via drill 0.61 pad 1.02)
  Top 0.254: 93.95,63 v93.95,57.61 93.95,53.8 94.27,53.48 94.27,46.81 93.64,46.18 C6.
  Bottom 0.254: v93.95,57.61 80.3,57.61 79.03,56.34
N$36  (via drill 0.81 pad 1.93)
  other vias: 59.66,63.64
N$37  (via drill 0.81 pad 1.93)
  other vias: 59.66,60.78
N$38  (via drill 0.81 pad 1.93)
  other vias: 59.66,57.92
N$39  (via drill 0.81 pad 1.93)
  other vias: 59.66,55.07
N$40  (via drill 0.81 pad 1.93)
  other vias: 59.66,52.21
N$41  (via drill 0.81 pad 1.93)
  other vias: 59.66,49.35
N$42  (via drill 0.81 pad 1.93)
  other vias: 59.66,46.49
N$43  (via drill 0.81 pad 1.93)
  other vias: 59.66,43.64
N$44  (via drill 0.81 pad 1.93)
  other vias: 59.66,40.78
N$45  (via drill 0.81 pad 1.93)
  other vias: 59.66,37.92
N$46  (via drill 0.81 pad 1.93)
  other vias: 59.66,35.06
N$47  (via drill 0.81 pad 1.93)
  other vias: 59.66,32.21
N$48  (via drill 0.81 pad 1.93)
  other vias: 59.66,29.35
N$49  (via drill 0.81 pad 1.93)
  other vias: 59.66,26.49
N$50  (via drill 0.81 pad 1.93)
  other vias: 59.66,23.63
N$51  (via drill 0.81 pad 1.93)
  other vias: 59.66,20.78
N$52  (via drill 0.81 pad 1.93)
  other vias: 59.66,17.92
N$53  (via drill 0.81 pad 1.93)
  other vias: 59.66,15.06
N$54  (via drill 0.81 pad 1.93)
  other vias: 59.66,12.2
N$55  (via drill 0.81 pad 1.93)
  other vias: 59.66,9.35
N$56  (via drill 0.81 pad 1.93)
  other vias: 59.66,6.49
N$58  (via drill 0.81 pad 1.93)
  other vias: 56.81,95.07
N$59  (via drill 0.81 pad 1.93)
  other vias: 56.81,92.21
N$60  (via drill 0.81 pad 1.93)
  other vias: 56.81,89.36
N$61  (via drill 0.81 pad 1.93)
  other vias: 56.81,86.5
N$62  (via drill 0.81 pad 1.93)
  other vias: 56.81,83.64
N$63  (via drill 0.81 pad 1.93)
  other vias: 56.81,80.78
N$64  (via drill 0.81 pad 1.93)
  other vias: 56.81,77.93
N$65  (via drill 0.81 pad 1.93)
  other vias: 56.81,75.07
N$66  (via drill 0.81 pad 1.93)
  other vias: 56.81,72.21
N$67  (via drill 0.81 pad 1.93)
  other vias: 56.81,69.35
N$68  (via drill 0.81 pad 1.93)
  other vias: 56.81,66.5
N$69  (via drill 0.81 pad 1.93)
  other vias: 56.81,63.64
N$70  (via drill 0.81 pad 1.93)
  other vias: 56.81,60.78
N$71  (via drill 0.81 pad 1.93)
  other vias: 56.81,57.92
N$72  (via drill 0.81 pad 1.93)
  other vias: 56.81,55.07
N$73  (via drill 0.81 pad 1.93)
  other vias: 56.81,52.21
N$74  (via drill 0.81 pad 1.93)
  other vias: 56.81,49.35
N$75  (via drill 0.81 pad 1.93)
  other vias: 56.81,46.49
N$76  (via drill 0.81 pad 1.93)
  other vias: 56.81,43.64
N$77  (via drill 0.81 pad 1.93)
  other vias: 56.81,40.78
N$78  (via drill 0.81 pad 1.93)
  other vias: 56.81,37.92
N$79  (via drill 0.81 pad 1.93)
  other vias: 56.81,35.06
N$80  (via drill 0.81 pad 1.93)
  other vias: 56.81,32.21
N$81  (via drill 0.81 pad 1.93)
  other vias: 56.81,29.35
N$82  (via drill 0.81 pad 1.93)
  other vias: 56.81,26.49
N$83  (via drill 0.81 pad 1.93)
  other vias: 56.81,23.63
N$84  (via drill 0.81 pad 1.93)
  other vias: 56.81,20.78
N$85  (via drill 0.81 pad 1.93)
  other vias: 56.81,17.92
N$86  (via drill 0.81 pad 1.93)
  other vias: 56.81,15.06
N$87  (via drill 0.81 pad 1.93)
  other vias: 56.81,12.2
N$88  (via drill 0.81 pad 1.93)
  other vias: 56.81,9.35
N$89  (via drill 0.81 pad 1.93)
  other vias: 56.81,6.49
N$91  (via drill 0.81 pad 1.93)
  other vias: 53.95,95.07
N$92  (via drill 0.81 pad 1.93)
  other vias: 53.95,92.21
N$93  (via drill 0.81 pad 1.93)
  other vias: 53.95,89.36
N$94  (via drill 0.81 pad 1.93)
  other vias: 53.95,86.5
N$95  (via drill 0.81 pad 1.93)
  other vias: 53.95,83.64
N$96  (via drill 0.81 pad 1.93)
  other vias: 53.95,80.78
N$97  (via drill 0.81 pad 1.93)
  other vias: 53.95,77.93
N$98  (via drill 0.81 pad 1.93)
  other vias: 53.95,75.07
N$99  (via drill 0.81 pad 1.93)
  other vias: 53.95,72.21
N$100  (via drill 0.81 pad 1.93)
  other vias: 53.95,69.35
N$101  (via drill 0.81 pad 1.93)
  other vias: 53.95,66.5
N$102  (via drill 0.81 pad 1.93)
  other vias: 53.95,63.64
N$103  (via drill 0.81 pad 1.93)
  other vias: 53.95,60.78
N$104  (via drill 0.81 pad 1.93)
  other vias: 53.95,57.92
N$105  (via drill 0.81 pad 1.93)
  other vias: 53.95,55.07
N$106  (via drill 0.81 pad 1.93)
  other vias: 53.95,52.21
N$107  (via drill 0.81 pad 1.93)
  other vias: 53.95,49.35
N$108  (via drill 0.81 pad 1.93)
  other vias: 53.95,46.49
N$109  (via drill 0.81 pad 1.93)
  other vias: 53.95,43.64
N$110  (via drill 0.81 pad 1.93)
  other vias: 53.95,40.78
N$111  (via drill 0.81 pad 1.93)
  other vias: 53.95,37.92
N$112  (via drill 0.81 pad 1.93)
  other vias: 53.95,35.06
N$113  (via drill 0.81 pad 1.93)
  other vias: 53.95,32.21
N$114  (via drill 0.81 pad 1.93)
  other vias: 53.95,29.35
N$115  (via drill 0.81 pad 1.93)
  other vias: 53.95,26.49
N$116  (via drill 0.81 pad 1.93)
  other vias: 53.95,23.63
N$117  (via drill 0.81 pad 1.93)
  other vias: 53.95,20.78
N$118  (via drill 0.81 pad 1.93)
  other vias: 53.95,17.92
N$119  (via drill 0.81 pad 1.93)
  other vias: 53.95,15.06
N$120  (via drill 0.81 pad 1.93)
  other vias: 53.95,12.2
N$121  (via drill 0.81 pad 1.93)
  other vias: 53.95,9.35
N$122  (via drill 0.81 pad 1.93)
  other vias: 53.95,6.49
N$124  (via drill 0.81 pad 1.93)
  other vias: 51.09,95.07
N$125  (via drill 0.81 pad 1.93)
  other vias: 51.09,92.21
N$126  (via drill 0.81 pad 1.93)
  other vias: 51.09,89.36
N$127  (via drill 0.81 pad 1.93)
  other vias: 51.09,86.5
N$128  (via drill 0.81 pad 1.93)
  other vias: 51.09,83.64
N$129  (via drill 0.81 pad 1.93)
  other vias: 51.09,80.78
N$130  (via drill 0.81 pad 1.93)
  other vias: 51.09,77.93
N$131  (via drill 0.81 pad 1.93)
  other vias: 51.09,75.07
N$132  (via drill 0.81 pad 1.93)
  other vias: 51.09,72.21
N$133  (via drill 0.81 pad 1.93)
  other vias: 51.09,69.35
N$134  (via drill 0.81 pad 1.93)
  other vias: 51.09,66.5
N$135  (via drill 0.81 pad 1.93)
  other vias: 51.09,63.64
N$136  (via drill 0.81 pad 1.93)
  other vias: 51.09,60.78
N$137  (via drill 0.81 pad 1.93)
  other vias: 51.09,57.92
N$138  (via drill 0.81 pad 1.93)
  other vias: 51.09,55.07
N$139  (via drill 0.81 pad 1.93)
  other vias: 51.09,52.21
N$140  (via drill 0.81 pad 1.93)
  other vias: 51.09,49.35
N$141  (via drill 0.81 pad 1.93)
  other vias: 51.09,46.49
N$142  (via drill 0.81 pad 1.93)
  other vias: 51.09,43.64
N$143  (via drill 0.81 pad 1.93)
  other vias: 51.09,40.78
N$144  (via drill 0.81 pad 1.93)
  other vias: 51.09,37.92
N$145  (via drill 0.81 pad 1.93)
  other vias: 51.09,35.06
N$146  (via drill 0.81 pad 1.93)
  other vias: 51.09,32.21
N$147  (via drill 0.81 pad 1.93)
  other vias: 51.09,29.35
N$148  (via drill 0.81 pad 1.93)
  other vias: 51.09,26.49
N$149  (via drill 0.81 pad 1.93)
  other vias: 51.09,23.63
N$150  (via drill 0.81 pad 1.93)
  other vias: 51.09,20.78
N$151  (via drill 0.81 pad 1.93)
  other vias: 51.09,17.92
N$152  (via drill 0.81 pad 1.93)
  other vias: 51.09,15.06
N$153  (via drill 0.81 pad 1.93)
  other vias: 51.09,12.2
N$154  (via drill 0.81 pad 1.93)
  other vias: 51.09,9.35
N$155  (via drill 0.81 pad 1.93)
  other vias: 51.09,6.49
N$157  (via drill 0.81 pad 1.93)
  other vias: 48.23,95.07
N$158  (via drill 0.81 pad 1.93)
  other vias: 48.23,92.21
N$159  (via drill 0.81 pad 1.93)
  other vias: 48.23,89.36
N$160  (via drill 0.81 pad 1.93)
  other vias: 48.23,86.5
N$161  (via drill 0.81 pad 1.93)
  other vias: 48.23,83.64
N$162  (via drill 0.81 pad 1.93)
  other vias: 48.23,80.78
N$163  (via drill 0.81 pad 1.93)
  other vias: 48.23,77.93
N$164  (via drill 0.81 pad 1.93)
  other vias: 48.23,75.07
N$165  (via drill 0.81 pad 1.93)
  other vias: 48.23,72.21
N$166  (via drill 0.81 pad 1.93)
  other vias: 48.23,69.35
N$167  (via drill 0.81 pad 1.93)
  other vias: 48.23,66.5
N$168  (via drill 0.81 pad 1.93)
  other vias: 48.23,63.64
N$169  (via drill 0.81 pad 1.93)
  other vias: 48.23,60.78
N$170  (via drill 0.81 pad 1.93)
  other vias: 48.23,57.92
N$171  (via drill 0.81 pad 1.93)
  other vias: 48.23,55.07
N$172  (via drill 0.81 pad 1.93)
  other vias: 48.23,52.21
N$173  (via drill 0.81 pad 1.93)
  other vias: 48.23,49.35
N$174  (via drill 0.81 pad 1.93)
  other vias: 48.23,46.49
N$175  (via drill 0.81 pad 1.93)
  other vias: 48.23,43.64
N$176  (via drill 0.81 pad 1.93)
  other vias: 48.23,40.78
N$177  (via drill 0.81 pad 1.93)
  other vias: 48.23,37.92
N$178  (via drill 0.81 pad 1.93)
  other vias: 48.23,35.06
N$179  (via drill 0.81 pad 1.93)
  other vias: 48.23,32.21
N$180  (via drill 0.81 pad 1.93)
  other vias: 48.23,29.35
N$181  (via drill 0.81 pad 1.93)
  other vias: 48.23,26.49
N$182  (via drill 0.81 pad 1.93)
  other vias: 48.23,23.63
N$183  (via drill 0.81 pad 1.93)
  other vias: 48.23,20.78
N$184  (via drill 0.81 pad 1.93)
  other vias: 48.23,17.92
N$185  (via drill 0.81 pad 1.93)
  other vias: 48.23,15.06
N$186  (via drill 0.81 pad 1.93)
  other vias: 48.23,12.2
N$187  (via drill 0.81 pad 1.93)
  other vias: 48.23,9.35
N$188  (via drill 0.81 pad 1.93)
  other vias: 48.23,6.49
N$190  (via drill 0.81 pad 1.93)
  other vias: 45.38,95.07
N$191  (via drill 0.81 pad 1.93)
  other vias: 45.38,92.21
N$192  (via drill 0.81 pad 1.93)
  other vias: 45.38,89.36
N$193  (via drill 0.81 pad 1.93)
  other vias: 45.38,86.5
N$194  (via drill 0.81 pad 1.93)
  other vias: 45.38,83.64
N$195  (via drill 0.81 pad 1.93)
  other vias: 45.38,80.78
N$196  (via drill 0.81 pad 1.93)
  other vias: 45.38,77.93
N$197  (via drill 0.81 pad 1.93)
  other vias: 45.38,75.07
N$198  (via drill 0.81 pad 1.93)
  other vias: 45.38,72.21
N$199  (via drill 0.81 pad 1.93)
  other vias: 45.38,69.35
N$200  (via drill 0.81 pad 1.93)
  other vias: 45.38,66.5
N$201  (via drill 0.81 pad 1.93)
  other vias: 45.38,63.64
N$202  (via drill 0.81 pad 1.93)
  other vias: 45.38,60.78
N$203  (via drill 0.81 pad 1.93)
  other vias: 45.38,57.92
N$204  (via drill 0.81 pad 1.93)
  other vias: 45.38,55.07
N$205  (via drill 0.81 pad 1.93)
  other vias: 45.38,52.21
N$206  (via drill 0.81 pad 1.93)
  other vias: 45.38,49.35
N$207  (via drill 0.81 pad 1.93)
  other vias: 45.38,46.49
N$208  (via drill 0.81 pad 1.93)
  other vias: 45.38,43.64
N$209  (via drill 0.81 pad 1.93)
  other vias: 45.38,40.78
N$210  (via drill 0.81 pad 1.93)
  other vias: 45.38,37.92
N$211  (via drill 0.81 pad 1.93)
  other vias: 45.38,35.06
N$212  (via drill 0.81 pad 1.93)
  other vias: 45.38,32.21
N$213  (via drill 0.81 pad 1.93)
  other vias: 45.38,29.35
N$214  (via drill 0.81 pad 1.93)
  other vias: 45.38,26.49
N$215  (via drill 0.81 pad 1.93)
  other vias: 45.38,23.63
N$216  (via drill 0.81 pad 1.93)
  other vias: 45.38,20.78
N$217  (via drill 0.81 pad 1.93)
  other vias: 45.38,17.92
N$218  (via drill 0.81 pad 1.93)
  other vias: 45.38,15.06
N$219  (via drill 0.81 pad 1.93)
  other vias: 45.38,12.2
N$220  (via drill 0.81 pad 1.93)
  other vias: 45.38,9.35
N$221  (via drill 0.81 pad 1.93)
  other vias: 45.38,6.49
N$223  (via drill 0.81 pad 1.93)
  other vias: 42.52,95.07
N$224  (via drill 0.81 pad 1.93)
  other vias: 42.52,92.21
N$225  (via drill 0.81 pad 1.93)
  other vias: 42.52,89.36
N$226  (via drill 0.81 pad 1.93)
  other vias: 42.52,86.5
N$227  (via drill 0.81 pad 1.93)
  other vias: 42.52,83.64
N$228  (via drill 0.81 pad 1.93)
  other vias: 42.52,80.78
N$229  (via drill 0.81 pad 1.93)
  other vias: 42.52,77.93
N$230  (via drill 0.81 pad 1.93)
  other vias: 42.52,75.07
N$231  (via drill 0.81 pad 1.93)
  other vias: 42.52,72.21
N$232  (via drill 0.81 pad 1.93)
  other vias: 42.52,69.35
N$233  (via drill 0.81 pad 1.93)
  other vias: 42.52,66.5
N$234  (via drill 0.81 pad 1.93)
  other vias: 42.52,63.64
N$235  (via drill 0.81 pad 1.93)
  other vias: 42.52,60.78
N$236  (via drill 0.81 pad 1.93)
  other vias: 42.52,57.92
N$237  (via drill 0.81 pad 1.93)
  other vias: 42.52,55.07
N$238  (via drill 0.81 pad 1.93)
  other vias: 42.52,52.21
N$239  (via drill 0.81 pad 1.93)
  other vias: 42.52,49.35
N$240  (via drill 0.81 pad 1.93)
  other vias: 42.52,46.49
N$241  (via drill 0.81 pad 1.93)
  other vias: 42.52,43.64
N$242  (via drill 0.81 pad 1.93)
  other vias: 42.52,40.78
N$243  (via drill 0.81 pad 1.93)
  other vias: 42.52,37.92
N$244  (via drill 0.81 pad 1.93)
  other vias: 42.52,35.06
N$245  (via drill 0.81 pad 1.93)
  other vias: 42.52,32.21
N$246  (via drill 0.81 pad 1.93)
  other vias: 42.52,29.35
N$247  (via drill 0.81 pad 1.93)
  other vias: 42.52,26.49
N$248  (via drill 0.81 pad 1.93)
  other vias: 42.52,23.63
N$249  (via drill 0.81 pad 1.93)
  other vias: 42.52,20.78
N$250  (via drill 0.81 pad 1.93)
  other vias: 42.52,17.92
N$251  (via drill 0.81 pad 1.93)
  other vias: 42.52,15.06
N$252  (via drill 0.81 pad 1.93)
  other vias: 42.52,12.2
N$253  (via drill 0.81 pad 1.93)
  other vias: 42.52,9.35
N$254  (via drill 0.81 pad 1.93)
  other vias: 42.52,6.49
N$256  (via drill 0.81 pad 1.93)
  other vias: 39.66,95.07
N$257  (via drill 0.81 pad 1.93)
  other vias: 39.66,92.21
N$258  (via drill 0.81 pad 1.93)
  other vias: 39.66,89.36
N$259  (via drill 0.81 pad 1.93)
  other vias: 39.66,86.5
N$260  (via drill 0.81 pad 1.93)
  other vias: 39.66,83.64
N$261  (via drill 0.81 pad 1.93)
  other vias: 39.66,80.78
N$262  (via drill 0.81 pad 1.93)
  other vias: 39.66,77.93
N$263  (via drill 0.81 pad 1.93)
  other vias: 39.66,75.07
N$264  (via drill 0.81 pad 1.93)
  other vias: 39.66,72.21
N$265  (via drill 0.81 pad 1.93)
  other vias: 39.66,69.35
N$266  (via drill 0.81 pad 1.93)
  other vias: 39.66,66.5
N$267  (via drill 0.81 pad 1.93)
  other vias: 39.66,63.64
N$268  (via drill 0.81 pad 1.93)
  other vias: 39.66,60.78
N$269  (via drill 0.81 pad 1.93)
  other vias: 39.66,57.92
N$270  (via drill 0.81 pad 1.93)
  other vias: 39.66,55.07
N$271  (via drill 0.81 pad 1.93)
  other vias: 39.66,52.21
N$272  (via drill 0.81 pad 1.93)
  other vias: 39.66,49.35
N$273  (via drill 0.81 pad 1.93)
  other vias: 39.66,46.49
N$274  (via drill 0.81 pad 1.93)
  other vias: 39.66,43.64
N$275  (via drill 0.81 pad 1.93)
  other vias: 39.66,40.78
N$276  (via drill 0.81 pad 1.93)
  other vias: 39.66,37.92
N$277  (via drill 0.81 pad 1.93)
  other vias: 39.66,35.06
N$278  (via drill 0.81 pad 1.93)
  other vias: 39.66,32.21
N$279  (via drill 0.81 pad 1.93)
  other vias: 39.66,29.35
N$280  (via drill 0.81 pad 1.93)
  other vias: 39.66,26.49
N$281  (via drill 0.81 pad 1.93)
  other vias: 39.66,23.63
N$282  (via drill 0.81 pad 1.93)
  other vias: 39.66,20.78
N$283  (via drill 0.81 pad 1.93)
  other vias: 39.66,17.92
N$284  (via drill 0.81 pad 1.93)
  other vias: 39.66,15.06
N$285  (via drill 0.81 pad 1.93)
  other vias: 39.66,12.2
N$286  (via drill 0.81 pad 1.93)
  other vias: 39.66,9.35
N$287  (via drill 0.81 pad 1.93)
  other vias: 39.66,6.49
N$289  (via drill 0.81 pad 1.93)
  other vias: 36.8,95.07
N$290  (via drill 0.81 pad 1.93)
  other vias: 36.8,92.21
N$291  (via drill 0.81 pad 1.93)
  other vias: 36.8,89.36
N$292  (via drill 0.81 pad 1.93)
  other vias: 36.8,86.5
N$293  (via drill 0.81 pad 1.93)
  other vias: 36.8,83.64
N$294  (via drill 0.81 pad 1.93)
  other vias: 36.8,80.78
N$295  (via drill 0.81 pad 1.93)
  other vias: 36.8,77.93
N$296  (via drill 0.81 pad 1.93)
  other vias: 36.8,75.07
N$297  (via drill 0.81 pad 1.93)
  other vias: 36.8,72.21
N$298  (via drill 0.81 pad 1.93)
  other vias: 36.8,69.35
N$299  (via drill 0.81 pad 1.93)
  other vias: 36.8,66.5
N$300  (via drill 0.81 pad 1.93)
  other vias: 36.8,63.64
N$301  (via drill 0.81 pad 1.93)
  other vias: 36.8,60.78
N$302  (via drill 0.81 pad 1.93)
  other vias: 36.8,57.92
N$303  (via drill 0.81 pad 1.93)
  other vias: 36.8,55.07
N$304  (via drill 0.81 pad 1.93)
  other vias: 36.8,52.21
N$305  (via drill 0.81 pad 1.93)
  other vias: 36.8,49.35
N$306  (via drill 0.81 pad 1.93)
  other vias: 36.8,46.49
N$307  (via drill 0.81 pad 1.93)
  other vias: 36.8,43.64
N$308  (via drill 0.81 pad 1.93)
  other vias: 36.8,40.78
N$309  (via drill 0.81 pad 1.93)
  other vias: 36.8,37.92
N$310  (via drill 0.81 pad 1.93)
  other vias: 36.8,35.06
N$311  (via drill 0.81 pad 1.93)
  other vias: 36.8,32.21
N$312  (via drill 0.81 pad 1.93)
  other vias: 36.8,29.35
N$313  (via drill 0.81 pad 1.93)
  other vias: 36.8,26.49
N$314  (via drill 0.81 pad 1.93)
  other vias: 36.8,23.63
N$315  (via drill 0.81 pad 1.93)
  other vias: 36.8,20.78
N$316  (via drill 0.81 pad 1.93)
  other vias: 36.8,17.92
N$317  (via drill 0.81 pad 1.93)
  other vias: 36.8,15.06
N$318  (via drill 0.81 pad 1.93)
  other vias: 36.8,12.2
N$319  (via drill 0.81 pad 1.93)
  other vias: 36.8,9.35
N$320  (via drill 0.81 pad 1.93)
  other vias: 36.8,6.49
N$322  (via drill 0.81 pad 1.93)
  other vias: 33.95,95.07
N$323  (via drill 0.81 pad 1.93)
  other vias: 33.95,92.21
N$324  (via drill 0.81 pad 1.93)
  other vias: 33.95,89.36
N$325  (via drill 0.81 pad 1.93)
  other vias: 33.95,86.5
N$326  (via drill 0.81 pad 1.93)
  other vias: 33.95,83.64
N$327  (via drill 0.81 pad 1.93)
  other vias: 33.95,80.78
N$328  (via drill 0.81 pad 1.93)
  other vias: 33.95,77.93
N$329  (via drill 0.81 pad 1.93)
  other vias: 33.95,75.07
N$330  (via drill 0.81 pad 1.93)
  other vias: 33.95,72.21
N$331  (via drill 0.81 pad 1.93)
  other vias: 33.95,69.35
N$332  (via drill 0.81 pad 1.93)
  other vias: 33.95,66.5
N$333  (via drill 0.81 pad 1.93)
  other vias: 33.95,63.64
N$334  (via drill 0.81 pad 1.93)
  other vias: 33.95,60.78
N$335  (via drill 0.81 pad 1.93)
  other vias: 33.95,57.92
N$336  (via drill 0.81 pad 1.93)
  other vias: 33.95,55.07
N$337  (via drill 0.81 pad 1.93)
  other vias: 33.95,52.21
N$338  (via drill 0.81 pad 1.93)
  other vias: 33.95,49.35
N$339  (via drill 0.81 pad 1.93)
  other vias: 33.95,46.49
N$340  (via drill 0.81 pad 1.93)
  other vias: 33.95,43.64
N$341  (via drill 0.81 pad 1.93)
  other vias: 33.95,40.78
N$342  (via drill 0.81 pad 1.93)
  other vias: 33.95,37.92
N$343  (via drill 0.81 pad 1.93)
  other vias: 33.95,35.06
N$344  (via drill 0.81 pad 1.93)
  other vias: 33.95,32.21
N$345  (via drill 0.81 pad 1.93)
  other vias: 33.95,29.35
N$346  (via drill 0.81 pad 1.93)
  other vias: 33.95,26.49
N$347  (via drill 0.81 pad 1.93)
  other vias: 33.95,23.63
N$348  (via drill 0.81 pad 1.93)
  other vias: 33.95,20.78
N$349  (via drill 0.81 pad 1.93)
  other vias: 33.95,17.92
N$350  (via drill 0.81 pad 1.93)
  other vias: 33.95,15.06
N$351  (via drill 0.81 pad 1.93)
  other vias: 33.95,12.2
N$352  (via drill 0.81 pad 1.93)
  other vias: 33.95,9.35
N$353  (via drill 0.81 pad 1.93)
  other vias: 33.95,6.49
N$355  (via drill 0.81 pad 1.93)
  other vias: 31.09,95.07
N$356  (via drill 0.81 pad 1.93)
  other vias: 31.09,92.21
N$357  (via drill 0.81 pad 1.93)
  other vias: 31.09,89.36
N$358  (via drill 0.81 pad 1.93)
  other vias: 31.09,86.5
N$359  (via drill 0.81 pad 1.93)
  other vias: 31.09,83.64
N$360  (via drill 0.81 pad 1.93)
  other vias: 31.09,80.78
N$361  (via drill 0.81 pad 1.93)
  other vias: 31.09,77.93
N$362  (via drill 0.81 pad 1.93)
  other vias: 31.09,75.07
N$363  (via drill 0.81 pad 1.93)
  other vias: 31.09,72.21
N$364  (via drill 0.81 pad 1.93)
  other vias: 31.09,69.35
N$365  (via drill 0.81 pad 1.93)
  other vias: 31.09,66.5
N$366  (via drill 0.81 pad 1.93)
  other vias: 31.09,63.64
N$367  (via drill 0.81 pad 1.93)
  other vias: 31.09,60.78
N$368  (via drill 0.81 pad 1.93)
  other vias: 31.09,57.92
N$369  (via drill 0.81 pad 1.93)
  other vias: 31.09,55.07
N$370  (via drill 0.81 pad 1.93)
  other vias: 31.09,52.21
N$371  (via drill 0.81 pad 1.93)
  other vias: 31.09,49.35
N$372  (via drill 0.81 pad 1.93)
  other vias: 31.09,46.49
N$373  (via drill 0.81 pad 1.93)
  other vias: 31.09,43.64
N$374  (via drill 0.81 pad 1.93)
  other vias: 31.09,40.78
N$375  (via drill 0.81 pad 1.93)
  other vias: 31.09,37.92
N$376  (via drill 0.81 pad 1.93)
  other vias: 31.09,35.06
N$377  (via drill 0.81 pad 1.93)
  other vias: 31.09,32.21
N$378  (via drill 0.81 pad 1.93)
  other vias: 31.09,29.35
N$379  (via drill 0.81 pad 1.93)
  other vias: 31.09,26.49
N$380  (via drill 0.81 pad 1.93)
  other vias: 31.09,23.63
N$381  (via drill 0.81 pad 1.93)
  other vias: 31.09,20.78
N$382  (via drill 0.81 pad 1.93)
  other vias: 31.09,17.92
N$383  (via drill 0.81 pad 1.93)
  other vias: 31.09,15.06
N$384  (via drill 0.81 pad 1.93)
  other vias: 31.09,12.2
N$385  (via drill 0.81 pad 1.93)
  other vias: 31.09,9.35
N$386  (via drill 0.81 pad 1.93)
  other vias: 31.09,6.49
N$388  (via drill 0.81 pad 1.93)
  other vias: 28.23,95.07
N$389  (via drill 0.81 pad 1.93)
  other vias: 28.23,92.21
N$390  (via drill 0.81 pad 1.93)
  other vias: 28.23,89.36
N$391  (via drill 0.81 pad 1.93)
  other vias: 28.23,86.5
N$392  (via drill 0.81 pad 1.93)
  other vias: 28.23,83.64
N$393  (via drill 0.81 pad 1.93)
  other vias: 28.23,80.78
N$394  (via drill 0.81 pad 1.93)
  other vias: 28.23,77.93
N$395  (via drill 0.81 pad 1.93)
  other vias: 28.23,75.07
N$396  (via drill 0.81 pad 1.93)
  other vias: 28.23,72.21
N$397  (via drill 0.81 pad 1.93)
  other vias: 28.23,69.35
N$398  (via drill 0.81 pad 1.93)
  other vias: 28.23,66.5
N$399  (via drill 0.81 pad 1.93)
  other vias: 28.23,63.64
N$400  (via drill 0.81 pad 1.93)
  other vias: 28.23,60.78
N$401  (via drill 0.81 pad 1.93)
  other vias: 28.23,57.92
N$402  (via drill 0.81 pad 1.93)
  other vias: 28.23,55.07
N$403  (via drill 0.81 pad 1.93)
  other vias: 28.23,52.21
N$404  (via drill 0.81 pad 1.93)
  other vias: 28.23,49.35
N$405  (via drill 0.81 pad 1.93)
  other vias: 28.23,46.49
N$406  (via drill 0.81 pad 1.93)
  other vias: 28.23,43.64
N$407  (via drill 0.81 pad 1.93)
  other vias: 28.23,40.78
N$408  (via drill 0.81 pad 1.93)
  other vias: 28.23,37.92
N$409  (via drill 0.81 pad 1.93)
  other vias: 28.23,35.06
N$410  (via drill 0.81 pad 1.93)
  other vias: 28.23,32.21
N$411  (via drill 0.81 pad 1.93)
  other vias: 28.23,29.35
N$412  (via drill 0.81 pad 1.93)
  other vias: 28.23,26.49
N$413  (via drill 0.81 pad 1.93)
  other vias: 28.23,23.63
N$414  (via drill 0.81 pad 1.93)
  other vias: 28.23,20.78
N$415  (via drill 0.81 pad 1.93)
  other vias: 28.23,17.92
N$416  (via drill 0.81 pad 1.93)
  other vias: 28.23,15.06
N$417  (via drill 0.81 pad 1.93)
  other vias: 28.23,12.2
N$418  (via drill 0.81 pad 1.93)
  other vias: 28.23,9.35
N$419  (via drill 0.81 pad 1.93)
  other vias: 28.23,6.49
N$421  (via drill 0.81 pad 1.93)
  other vias: 25.37,95.07
N$422  (via drill 0.81 pad 1.93)
  other vias: 25.37,92.21
N$423  (via drill 0.81 pad 1.93)
  other vias: 25.37,89.36
N$424  (via drill 0.81 pad 1.93)
  other vias: 25.37,86.5
N$425  (via drill 0.81 pad 1.93)
  other vias: 25.37,83.64
N$426  (via drill 0.81 pad 1.93)
  other vias: 25.37,80.78
N$427  (via drill 0.81 pad 1.93)
  other vias: 25.37,77.93
N$428  (via drill 0.81 pad 1.93)
  other vias: 25.37,75.07
N$429  (via drill 0.81 pad 1.93)
  other vias: 25.37,72.21
N$430  (via drill 0.81 pad 1.93)
  other vias: 25.37,69.35
N$431  (via drill 0.81 pad 1.93)
  other vias: 25.37,66.5
N$432  (via drill 0.81 pad 1.93)
  other vias: 25.37,63.64
N$433  (via drill 0.81 pad 1.93)
  other vias: 25.37,60.78
N$434  (via drill 0.81 pad 1.93)
  other vias: 25.37,57.92
N$435  (via drill 0.81 pad 1.93)
  other vias: 25.37,55.07
N$436  (via drill 0.81 pad 1.93)
  other vias: 25.37,52.21
N$437  (via drill 0.81 pad 1.93)
  other vias: 25.37,49.35
N$438  (via drill 0.81 pad 1.93)
  other vias: 25.37,46.49
N$439  (via drill 0.81 pad 1.93)
  other vias: 25.37,43.64
N$440  (via drill 0.81 pad 1.93)
  other vias: 25.37,40.78
N$441  (via drill 0.81 pad 1.93)
  other vias: 25.37,37.92
N$442  (via drill 0.81 pad 1.93)
  other vias: 25.37,35.06
N$443  (via drill 0.81 pad 1.93)
  other vias: 25.37,32.21
N$444  (via drill 0.81 pad 1.93)
  other vias: 25.37,29.35
N$445  (via drill 0.81 pad 1.93)
  other vias: 25.37,26.49
N$446  (via drill 0.81 pad 1.93)
  other vias: 25.37,23.63
N$447  (via drill 0.81 pad 1.93)
  other vias: 25.37,20.78
N$448  (via drill 0.81 pad 1.93)
  other vias: 25.37,17.92
N$449  (via drill 0.81 pad 1.93)
  other vias: 25.37,15.06
N$450  (via drill 0.81 pad 1.93)
  other vias: 25.37,12.2
N$451  (via drill 0.81 pad 1.93)
  other vias: 25.37,9.35
N$452  (via drill 0.81 pad 1.93)
  other vias: 25.37,6.49
N$454  (via drill 0.81 pad 1.93)
  other vias: 22.52,95.07
N$455  (via drill 0.81 pad 1.93)
  other vias: 22.52,92.21
N$456  (via drill 0.81 pad 1.93)
  other vias: 22.52,89.36
N$457  (via drill 0.81 pad 1.93)
  other vias: 22.52,86.5
N$458  (via drill 0.81 pad 1.93)
  other vias: 22.52,83.64
N$459  (via drill 0.81 pad 1.93)
  other vias: 22.52,80.78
